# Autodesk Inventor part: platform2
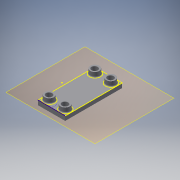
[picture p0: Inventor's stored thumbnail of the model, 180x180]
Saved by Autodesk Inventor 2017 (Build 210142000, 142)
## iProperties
Created: 2017-05
Part Number: platform2
Material: Generic
Document SubType Name: Modeling
Designer: 1717440
Density: 1 g/cm^3
Appearance: Default
Author: 1717440
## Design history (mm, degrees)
workplane "Work Plane2"
sketch "Sketch4"
  geometry: L1 (-19.592, 26.016)-(-19.592, -98.984) reference; L2 (-19.592, -98.984)-(40.408, -98.984) reference; L3 (40.408, -98.984)-(40.408, 26.016) reference; L4 (40.408, 26.016)-(-19.592, 26.016) reference; C1 r 10 at (-7.092, -86.484) reference; C2 r 10 at (27.908, -86.484) reference; C3 r 10 at (-7.092, 13.516) reference; C4 r 10 at (27.908, 13.516) reference; C5 r 6.425 at (-7.092, -86.484); C6 r 6.425 at (-7.092, 13.516); C7 r 6.425 at (27.908, 13.516); C8 r 6.425 at (27.908, -86.484); 1 further point
  constraints: 4 centre point, 3 coincident
  dimensions: "d19" = 12.85 diameter of C5; "d20" = 12.85 diameter of C6
extrude "Extrusion4" new body sketch "Sketch4" distance "d21" = 10; taper "d22" = 0 deg
sketch "Sketch5"
  geometry: C1 r 10 at (-27.908, 13.516) reference; C2 r 10 at (7.092, 13.516) reference; C3 r 10 at (-27.908, -86.484) reference; C4 r 10 at (7.092, -86.484) reference; C5 r 10 at (7.092, 13.516) reference; C6 r 6.425 at (7.092, 13.516); C7 r 6.425 at (-27.908, 13.516); C8 r 6.425 at (-27.908, -86.484); C9 r 6.425 at (7.092, -86.484); 1 further point
  constraints: 4 centre point, 4 coincident
  dimensions: "d23" = 12.85 diameter of C6; "d24" = 12.85 diameter of C8
extrude "Extrusion5" join sketch "Sketch5" distance "d25" = 20; taper "d26" = 0 deg
fillet "Fillet1" dims "d27" = 2
fillet "Fillet2" dims "d28" = 1
sketch "Sketch6"
  geometry: L1 (-19.592, 26.016)-(-19.592, -98.984) reference; L2 (-19.592, -98.984)-(40.408, -98.984) reference; L3 (40.408, -98.984)-(40.408, 26.016) reference; L4 (40.408, 26.016)-(-19.592, 26.016) reference; L5 (-19.592, -98.984)-(40.408, -98.984); L6 (10.408, -98.984)-(10.408, -86.484); C1 r 12 at (-7.092, -86.484) reference; C2 r 12 at (-7.092, 13.516) reference; C3 r 12 at (27.908, 13.516) reference; C4 r 12 at (27.908, -86.484) reference; 1 further point
  constraints: 4 end point, 1 horizontal, 1 midpoint, 1 vertical
body "Solid2"
node "Reference1"
node "Reference2"
node "Reference3"
node "Reference4"
node "Reference5"
